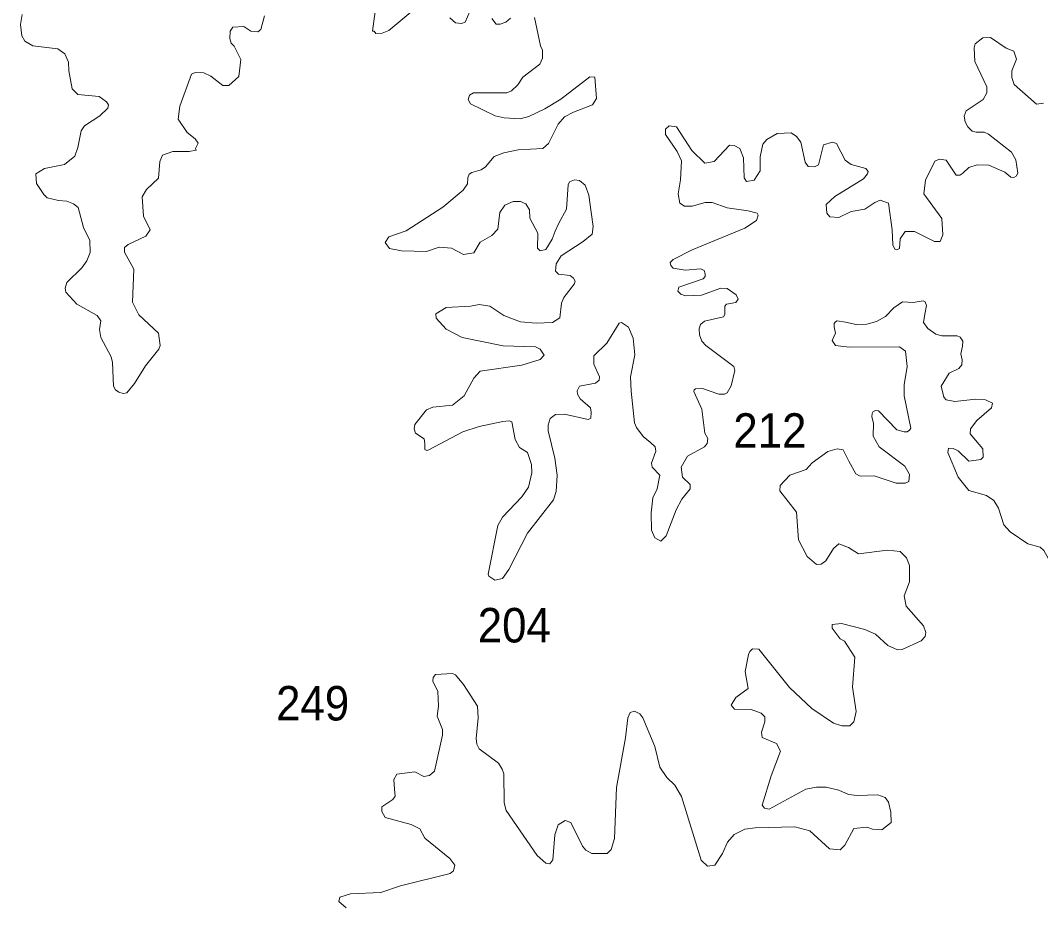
# Model space of a CAD drawing. Extents: x 499.9 to 555.3, y 9281.5 to 9336.8.
# Drawn here: x 513.714 to 518.449, y 9328.796 to 9332.901 of the extents above; entities that cross this region are included whole.
import ezdxf

# ---------------------------------------------------------------- set-up
doc = ezdxf.new("R2010")
doc.units = 0
doc.header["$LTSCALE"] = 0.064
doc.layers.add('2', color=7, linetype='Continuous', lineweight=13)
doc.layers.add('21', color=7, linetype='Continuous')

msp = doc.modelspace()

# ---------------------------------------------------------------- linework, layer by layer
at = {"layer": '2'}
for points in [[(515.8319, 9333.018), (515.7778, 9332.8934), (515.7611, 9332.8861), (515.7337, 9332.8903), (515.7071, 9332.9134)], [(515.573, 9332.978), (515.4247, 9332.8536), (515.3929, 9332.8424), (515.3635, 9332.8409), (515.3561, 9332.8513), (515.3488, 9332.8514), (515.3604, 9332.9429)], [(514.0368, 9331.8802), (514.0064, 9331.9406), (513.9823, 9332.0335), (513.9604, 9332.0511), (513.9302, 9332.0633), (513.8905, 9332.0656), (513.839, 9332.0789), (513.8221, 9332.0944), (513.7893, 9332.1441), (513.7861, 9332.1901), (513.8254, 9332.214), (513.919, 9332.2328), (513.9661, 9332.272), (513.981, 9332.3123), (513.9961, 9332.3891), (514.0123, 9332.4128), (514.083, 9332.4587), (514.1191, 9332.4949), (514.1225, 9332.5096), (514.1142, 9332.5228), (514.0803, 9332.5483), (513.9805, 9332.5574), (513.9547, 9332.5837), (513.9386, 9332.6671), (513.938, 9332.707), (513.92, 9332.7456), (513.8871, 9332.7687), (513.7712, 9332.7838), (513.7347, 9332.8042), (513.7215, 9332.8293), (513.7141, 9332.8821), (513.7218, 9332.9286)], [(514.8477, 9332.9223), (514.8294, 9332.8589), (514.8162, 9332.848), (514.7834, 9332.8505), (514.7514, 9332.8725), (514.7003, 9332.8695), (514.6871, 9332.8515), (514.6864, 9332.817), (514.6929, 9332.7963), (514.7059, 9332.7821), (514.7371, 9332.7198), (514.7279, 9332.6416), (514.6813, 9332.5991), (514.6529, 9332.5988), (514.5978, 9332.6427), (514.5648, 9332.6581), (514.5247, 9332.6591), (514.5075, 9332.6514), (514.4541, 9332.504), (514.446, 9332.4428), (514.4886, 9332.3812), (514.5247, 9332.3525), (514.5384, 9332.332), (514.526, 9332.3065), (514.5294, 9332.2998), (514.4976, 9332.2932), (514.4221, 9332.293), (514.3741, 9332.2764), (514.3619, 9332.2461), (514.3549, 9332.1692), (514.2986, 9332.117), (514.2791, 9332.083), (514.2853, 9331.993), (514.3163, 9331.9297), (514.2955, 9331.8998), (514.2143, 9331.8622), (514.1979, 9331.8481), (514.1975, 9331.8258), (514.2405, 9331.748), (514.2349, 9331.5945), (514.263, 9331.5357), (514.355, 9331.4506), (514.3632, 9331.3938), (514.3571, 9331.3769), (514.2948, 9331.2984), (514.2438, 9331.2174), (514.2085, 9331.1745), (514.191, 9331.1714), (514.1702, 9331.1767), (514.1555, 9331.1884), (514.1455, 9331.2047), (514.1419, 9331.3149), (514.1353, 9331.3413), (514.0878, 9331.4313), (514.0816, 9331.468), (514.0868, 9331.5083), (514.0702, 9331.5322), (513.9765, 9331.585), (513.9252, 9331.6405), (513.9225, 9331.6594)], [(515.7891, 9332.1431), (515.791, 9332.1713), (515.7969, 9332.1877), (515.8094, 9332.1962), (515.852, 9332.2087), (515.8724, 9332.2222), (515.9125, 9332.2694), (515.957, 9332.2874), (516.0239, 9332.3012), (516.139, 9332.3071), (516.1647, 9332.3299), (516.2106, 9332.4198), (516.2392, 9332.4533), (516.2804, 9332.4758), (516.369, 9332.5091), (516.3875, 9332.5385), (516.3795, 9332.6376), (516.3566, 9332.6399), (516.222, 9332.5361), (516.148, 9332.491), (516.0739, 9332.4552), (516.0335, 9332.4446), (515.9595, 9332.4488), (515.9182, 9332.4588), (515.8036, 9332.5136), (515.7916, 9332.5338), (515.7979, 9332.5544), (515.817, 9332.5652), (515.9724, 9332.5654), (515.9932, 9332.5742), (516.0225, 9332.6017), (516.0461, 9332.6374), (516.1241, 9332.6987), (516.1375, 9332.7262), (516.1377, 9332.7626), (516.1281, 9332.7825), (516.0999, 9332.9153)], [(515.988, 9332.9108), (515.9663, 9332.8936), (515.9404, 9332.8838), (515.9225, 9332.8843), (515.9025, 9332.9103)], [(518.4617, 9332.5177), (518.4292, 9332.512), (518.3257, 9332.6036), (518.3153, 9332.6362), (518.3151, 9332.667), (518.3369, 9332.7215), (518.3249, 9332.7584), (518.2889, 9332.7727), (518.2163, 9332.8212), (518.1809, 9332.8201), (518.1455, 9332.7922), (518.1401, 9332.7738), (518.1432, 9332.7099), (518.1998, 9332.5935), (518.2, 9332.5649)], [(518.2, 9332.5649), (518.1828, 9332.5351), (518.1036, 9332.482), (518.0946, 9332.4574), (518.0988, 9332.43), (518.1106, 9332.4081)], [(518.1106, 9332.4081), (518.1316, 9332.3877), (518.1494, 9332.3832), (518.1875, 9332.3825), (518.2067, 9332.3741), (518.3143, 9332.2904), (518.334, 9332.255), (518.3434, 9332.1931), (518.3355, 9332.1791), (518.3252, 9332.1725), (518.3114, 9332.1745), (518.2824, 9332.1979), (518.2082, 9332.2299), (518.1547, 9332.2311), (518.1153, 9332.2185), (518.0873, 9332.1931), (518.0734, 9332.1828), (518.0574, 9332.1841), (518.0108, 9332.2529), (517.9792, 9332.2577), (517.9587, 9332.2484), (517.9141, 9332.1595), (517.9076, 9332.0974), (517.9901, 9331.9826), (517.9951, 9331.9066), (517.9821, 9331.875), (517.9565, 9331.8755), (517.8638, 9331.9219), (517.8204, 9331.9216), (517.7975, 9331.8877), (517.7942, 9331.8434), (517.7822, 9331.837), (517.7728, 9331.8407), (517.7625, 9331.8608), (517.7596, 9331.9306), (517.7423, 9332.0529), (517.7045, 9332.0667), (517.6798, 9332.0574), (517.6331, 9332.0257), (517.5702, 9332.0144), (517.5128, 9331.9877), (517.471, 9331.9898), (517.4568, 9332.0067), (517.4534, 9332.0474), (517.4944, 9332.085), (517.6268, 9332.1671), (517.6459, 9332.1892), (517.6479, 9332.2005), (517.6374, 9332.2142), (517.5703, 9332.2329), (517.5417, 9332.2536), (517.501, 9332.3305), (517.4834, 9332.3358), (517.4415, 9332.3246), (517.4174, 9332.2317), (517.3998, 9332.2218), (517.3706, 9332.2243), (517.356, 9332.2435), (517.3367, 9332.3361), (517.316, 9332.3625), (517.2909, 9332.379), (517.2266, 9332.3769), (517.1788, 9332.3487), (517.1597, 9332.3279), (517.147, 9332.2685), (517.1479, 9332.2036), (517.1199, 9332.1601), (517.0844, 9332.1547), (517.0731, 9332.1713), (517.0703, 9332.2644), (517.0537, 9332.3077), (517.0265, 9332.3214), (517.0048, 9332.323), (516.9332, 9332.2473), (516.8906, 9332.2393), (516.8305, 9332.2974), (516.7598, 9332.4077), (516.7255, 9332.4115), (516.708, 9332.3964), (516.7078, 9332.3713), (516.762, 9332.2926), (516.7823, 9332.2495), (516.7777, 9332.1612), (516.7666, 9332.0975), (516.7746, 9332.0531), (516.7961, 9332.0403), (516.8323, 9332.0402), (516.8915, 9332.0574), (516.924, 9332.0574), (516.994, 9332.0322), (517.0924, 9332.0186), (517.1327, 9332.0069), (517.1382, 9331.9982), (517.1298, 9331.9739), (517.0758, 9331.937)], [(515.8886, 9330.3239), (515.885, 9330.3325), (515.9294, 9330.5584), (515.9511, 9330.5979), (516.0417, 9330.6915), (516.0727, 9330.7363), (516.0883, 9330.8035), (516.0867, 9330.8416), (516.0673, 9330.8972), (516.0304, 9330.921), (516.0104, 9330.9571), (515.9953, 9331.0401), (515.9828, 9331.0444), (515.9532, 9331.0416), (515.8425, 9331.0185), (515.767, 9330.9934), (515.61, 9330.9091), (515.6006, 9330.907), (515.5914, 9330.9113), (515.5905, 9330.9389), (515.5878, 9330.9609), (515.547, 9330.9861), (515.5412, 9331.0066), (515.5443, 9331.0277), (515.599, 9331.0949), (515.6285, 9331.1073), (515.7191, 9331.1173), (515.7742, 9331.1598), (515.818, 9331.2426), (515.8484, 9331.2744), (516.0408, 9331.3021), (516.1269, 9331.3284), (516.145, 9331.3481), (516.1269, 9331.3757), (516.1041, 9331.3873), (515.9546, 9331.3926), (515.7646, 9331.4309), (515.6908, 9331.4685), (515.6429, 9331.5207), (515.6415, 9331.5396), (515.6907, 9331.5693), (515.8035, 9331.5754), (515.8425, 9331.5832), (515.8921, 9331.5755), (515.9579, 9331.5332), (516.0344, 9331.5035), (516.1074, 9331.4974), (516.1838, 9331.5004), (516.2174, 9331.5219), (516.2253, 9331.5899), (516.2357, 9331.6165), (516.2845, 9331.6781), (516.2886, 9331.6915), (516.2818, 9331.7055), (516.2658, 9331.718), (516.2109, 9331.725), (516.197, 9331.7386), (516.2, 9331.7727), (516.2244, 9331.8098), (516.3261, 9331.875), (516.367, 9331.9104), (516.3726, 9331.9448), (516.3628, 9332.012), (516.3523, 9332.0902), (516.3348, 9332.1371), (516.3091, 9332.159), (516.2855, 9332.162), (516.2624, 9332.1521), (516.2558, 9332.1389), (516.2487, 9332.0252), (516.2134, 9331.9605), (516.1958, 9331.9243), (516.1826, 9331.8865), (516.1534, 9331.8381), (516.1268, 9331.832), (516.1142, 9331.8445), (516.1151, 9331.9143), (516.0777, 9331.9838), (516.0767, 9332.0232), (516.0595, 9332.0509), (516.0356, 9332.0608), (516.001, 9332.0606), (515.9624, 9332.0442), (515.9394, 9332.0105), (515.9301, 9331.933), (515.9027, 9331.9039), (515.8482, 9331.8727), (515.8182, 9331.8229), (515.7702, 9331.816), (515.7151, 9331.8455), (515.658, 9331.8488), (515.5981, 9331.83), (515.4835, 9331.8318), (515.4265, 9331.843), (515.4064, 9331.8718)], [(515.4064, 9331.8718), (515.4241, 9331.897), (515.5043, 9331.9256), (515.674, 9332.0349), (515.7689, 9332.114), (515.7891, 9332.1431)], [(517.0758, 9331.937), (516.8324, 9331.8367), (516.744, 9331.7925), (516.7303, 9331.7784), (516.7329, 9331.7642), (516.7443, 9331.7522)], [(513.9225, 9331.6594), (513.9289, 9331.6851), (513.9997, 9331.7531), (514.0228, 9331.7862), (514.0382, 9331.8253), (514.0368, 9331.8802)], [(516.7443, 9331.7522), (516.7998, 9331.7425), (516.8724, 9331.7484), (516.8877, 9331.7416), (516.8915, 9331.7261), (516.8914, 9331.7138), (516.8834, 9331.7031), (516.7699, 9331.6638), (516.7654, 9331.6456), (516.7796, 9331.632), (516.8015, 9331.6232), (516.8753, 9331.6275), (516.9651, 9331.6596), (516.9947, 9331.6576), (517.0362, 9331.6288), (517.0446, 9331.6076), (517.0346, 9331.5925), (516.9916, 9331.5848), (516.9827, 9331.5765), (516.9835, 9331.537), (516.9769, 9331.5259), (516.889, 9331.5059), (516.8698, 9331.4903), (516.8636, 9331.4703), (516.8653, 9331.4434), (516.8767, 9331.4142), (516.8951, 9331.3927), (517.0256, 9331.2967), (517.0303, 9331.2769), (517.013, 9331.2062), (516.9938, 9331.1744), (516.9821, 9331.1681), (516.9558, 9331.1681), (516.8802, 9331.1946), (516.8473, 9331.1932), (516.8409, 9331.1876), (516.8402, 9331.1801), (516.8766, 9331.0978), (516.8904, 9330.9868), (516.9047, 9330.962), (516.902, 9330.9388), (516.8883, 9330.9242), (516.8102, 9330.8802), (516.7809, 9330.8297), (516.7869, 9330.7826), (516.8229, 9330.7488), (516.8219, 9330.7287), (516.784, 9330.6809), (516.7569, 9330.6316), (516.7109, 9330.511), (516.6867, 9330.486), (516.658, 9330.5019), (516.6423, 9330.5369), (516.6408, 9330.6178), (516.6499, 9330.6872), (516.6698, 9330.7288), (516.6818, 9330.7915), (516.6458, 9330.8291), (516.643, 9330.848), (516.6637, 9330.904), (516.6597, 9330.9227), (516.6387, 9330.9431), (516.6036, 9330.9712), (516.5729, 9331.0129), (516.5644, 9331.0351), (516.549, 9331.1811), (516.5458, 9331.248), (516.5657, 9331.3509), (516.5576, 9331.428), (516.5358, 9331.4777), (516.5034, 9331.4997), (516.4923, 9331.4967), (516.4359, 9331.4045), (516.3752, 9331.346), (516.3751, 9331.3064), (516.4013, 9331.2476), (516.3994, 9331.2323), (516.3828, 9331.2185), (516.3092, 9331.2048), (516.2974, 9331.1829), (516.2996, 9331.1671), (516.3125, 9331.1464), (516.3599, 9331.1046), (516.3634, 9331.0848), (516.3617, 9331.0568), (516.3493, 9331.0504), (516.2388, 9331.0757), (516.1973, 9331.0739), (516.1726, 9331.0541), (516.1635, 9331.0239), (516.1634, 9330.9984), (516.195, 9330.8703), (516.206, 9330.7915), (516.2, 9330.7161), (516.1888, 9330.6769)], [(517.2393, 9330.72), (517.2407, 9330.7448), (517.2858, 9330.7914), (517.361, 9330.8177), (517.3881, 9330.85), (517.4618, 9330.9023), (517.505, 9330.914), (517.5332, 9330.9102), (517.5595, 9330.8575), (517.5921, 9330.7985), (517.6109, 9330.7874), (517.6759, 9330.7894), (517.7778, 9330.7542), (517.8208, 9330.7542), (517.8377, 9330.7623), (517.8406, 9330.795), (517.8183, 9330.8335), (517.6991, 9330.9232), (517.6722, 9330.9731), (517.6736, 9331.0336), (517.6659, 9331.0628), (517.6673, 9331.0782), (517.6725, 9331.0878), (517.6836, 9331.0915), (517.6967, 9331.0897), (517.7814, 9331.003), (517.816, 9330.9933), (517.8292, 9330.9924), (517.8405, 9331.0005), (517.8465, 9331.0096), (517.8153, 9331.16), (517.8158, 9331.2103), (517.8294, 9331.2968), (517.8214, 9331.3666), (517.7937, 9331.3874), (517.5599, 9331.386), (517.4977, 9331.394), (517.4815, 9331.4171), (517.4968, 9331.4505), (517.4906, 9331.4798), (517.4906, 9331.4962), (517.4963, 9331.5033), (517.5053, 9331.5074), (517.544, 9331.5021), (517.5932, 9331.4911), (517.642, 9331.4931), (517.6879, 9331.5055), (517.7286, 9331.5273), (517.7676, 9331.5674), (517.8083, 9331.5954), (517.8574, 9331.593), (517.9042, 9331.6003), (517.9132, 9331.5963), (517.9199, 9331.5794), (517.9109, 9331.538), (517.9055, 9331.4996), (517.9254, 9331.4723), (517.962, 9331.4459), (517.9904, 9331.4389), (518.0618, 9331.4382), (518.0752, 9331.4314), (518.0872, 9331.413), (518.0864, 9331.3905), (518.0792, 9331.3544), (518.0852, 9331.327), (518.084, 9331.3038), (518.0696, 9331.286), (518.025, 9331.2645), (517.9877, 9331.2042), (518.0002, 9331.154), (518.0103, 9331.1409), (518.0501, 9331.1331), (518.1482, 9331.1439), (518.1932, 9331.1408), (518.2254, 9331.1257), (518.2214, 9331.1046), (518.1533, 9331.0458), (518.1237, 9331.0077), (518.1216, 9330.9845), (518.1807, 9330.9139), (518.183, 9330.8751), (518.1716, 9330.8652), (518.1159, 9330.8576), (518.0657, 9330.9044), (518.0438, 9330.916), (518.021, 9330.9177), (518.0179, 9330.8979), (518.0668, 9330.7829), (518.1162, 9330.7209), (518.1972, 9330.6982), (518.2321, 9330.6743), (518.254, 9330.6386), (518.2786, 9330.5616), (518.307, 9330.5285), (518.3899, 9330.4735)], [(517.431, 9330.3786), (517.4094, 9330.3771), (517.3661, 9330.4144), (517.3259, 9330.4929), (517.3156, 9330.6199), (517.2393, 9330.72)], [(516.1888, 9330.6769), (516.0683, 9330.5233), (515.9802, 9330.3547), (515.9514, 9330.3122), (515.9157, 9330.3056), (515.8886, 9330.3239)], [(516.5334, 9329.6668), (516.5448, 9329.6909), (516.5644, 9329.6982), (516.5885, 9329.6855), (516.6028, 9329.6663), (516.6581, 9329.5334), (516.6822, 9329.438), (516.714, 9329.3902), (516.7508, 9329.3544), (516.7822, 9329.301), (516.8728, 9329.0064), (516.9022, 9328.9784), (516.9369, 9328.9834), (516.9732, 9329.0369), (516.9951, 9329.0897), (517.0266, 9329.1262), (517.0769, 9329.1497), (517.1238, 9329.1561), (517.3089, 9329.1608), (517.378, 9329.1428), (517.4694, 9329.0597), (517.5181, 9329.055), (517.5397, 9329.0767), (517.5822, 9329.153), (517.6419, 9329.1594), (517.6689, 9329.15), (517.7126, 9329.1469), (517.7546, 9329.181), (517.7545, 9329.2286), (517.7422, 9329.2748), (517.7277, 9329.2968), (517.6939, 9329.3089), (517.5981, 9329.3059), (517.5576, 9329.3116), (517.512, 9329.3314), (517.4532, 9329.3454), (517.4086, 9329.3456), (517.3594, 9329.3356), (517.1889, 9329.2428), (517.1677, 9329.2475), (517.1574, 9329.2614), (517.198, 9329.3973), (517.2417, 9329.5118), (517.2228, 9329.5475), (517.1565, 9329.5756), (517.1534, 9329.6003), (517.169, 9329.648), (517.1687, 9329.672), (517.1515, 9329.6876), (517.1062, 9329.7049), (517.0284, 9329.7071), (517.0134, 9329.7255), (517.0339, 9329.7604), (517.091, 9329.8033), (517.077, 9329.8811), (517.0931, 9329.9598), (517.0994, 9329.9736), (517.1118, 9329.9864), (517.1412, 9329.9858), (517.2842, 9329.8071), (517.3871, 9329.7096), (517.4875, 9329.6417), (517.5257, 9329.6291), (517.5636, 9329.6293), (517.5828, 9329.6482), (517.5924, 9329.6957), (517.5766, 9329.8096), (517.5874, 9329.9472), (517.5393, 9330.0223), (517.5185, 9330.0334), (517.4816, 9330.0818), (517.4819, 9330.0995), (517.5244, 9330.1039), (517.6338, 9330.0761), (517.6825, 9330.054), (517.7399, 9330.0019), (517.7841, 9329.9824), (517.8062, 9329.983), (517.8941, 9330.0233), (517.9139, 9330.0435), (517.9168, 9330.0618), (517.9058, 9330.0936), (517.8244, 9330.1845), (517.8153, 9330.2325), (517.8407, 9330.2981), (517.8407, 9330.3737), (517.8272, 9330.4084), (517.7974, 9330.4377), (517.7389, 9330.4436), (517.6043, 9330.4275), (517.5567, 9330.4568), (517.513, 9330.4734), (517.4875, 9330.4516), (517.4518, 9330.394), (517.431, 9330.3786)], [(518.3899, 9330.4735), (518.447, 9330.4579), (518.4635, 9330.4432), (518.4848, 9330.4033), (518.5014, 9330.3531), (518.5599, 9330.2972)], [(515.226, 9328.7849), (515.1926, 9328.8142), (515.1959, 9328.8344), (515.2468, 9328.8509), (515.3873, 9328.8573), (515.4788, 9328.8872), (515.7079, 9328.9447), (515.7242, 9328.9572), (515.7296, 9328.9833), (515.7075, 9329.0147), (515.5908, 9329.1081), (515.5671, 9329.1517), (515.5273, 9329.1723), (515.4071, 9329.2036), (515.3914, 9329.2325), (515.3921, 9329.2535), (515.4421, 9329.2877), (515.453, 9329.3031), (515.45, 9329.336), (515.4473, 9329.3805), (515.4605, 9329.406), (515.5442, 9329.4156), (515.5867, 9329.3952), (515.6124, 9329.3985), (515.6353, 9329.4186), (515.6731, 9329.5855), (515.6728, 9329.6128), (515.6476, 9329.6749), (515.6538, 9329.7213), (515.6508, 9329.7882), (515.6289, 9329.8367), (515.6302, 9329.8541), (515.6399, 9329.8677), (515.719, 9329.8724), (515.7335, 9329.8658), (515.7705, 9329.8207), (515.835, 9329.7207), (515.8385, 9329.6664), (515.829, 9329.5709), (515.8317, 9329.5438), (515.8433, 9329.5226), (515.9332, 9329.4558), (515.9501, 9329.4292), (515.958, 9329.4074), (515.9595, 9329.2725), (515.9679, 9329.237), (516.1125, 9329.0274), (516.1527, 9328.9923), (516.1709, 9328.9897), (516.1852, 9329.0083), (516.194, 9329.1246), (516.2097, 9329.1703), (516.2428, 9329.1908), (516.2681, 9329.1814), (516.3224, 9329.0719), (516.3377, 9329.0528), (516.3662, 9329.0369), (516.4374, 9329.0375)], [(516.4374, 9329.0375), (516.4558, 9329.0561), (516.4718, 9329.1069), (516.4801, 9329.3432), (516.5227, 9329.5741), (516.5334, 9329.6668)]]:
    msp.add_lwpolyline(points, dxfattribs=at)

# ---------------------------------------------------------------- texts
at = {"layer": '21', "width": 0.95}
for s, p in [('212', (517.0228, 9330.9191)), ('204', (515.8367, 9330.0162)), ('249', (514.9009, 9329.6543))]:
    msp.add_text(s, height=0.16, dxfattribs=at).set_placement(p)

doc.saveas('drawing.dxf')
